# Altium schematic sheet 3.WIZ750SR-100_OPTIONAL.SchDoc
size A4; Team: Wiki
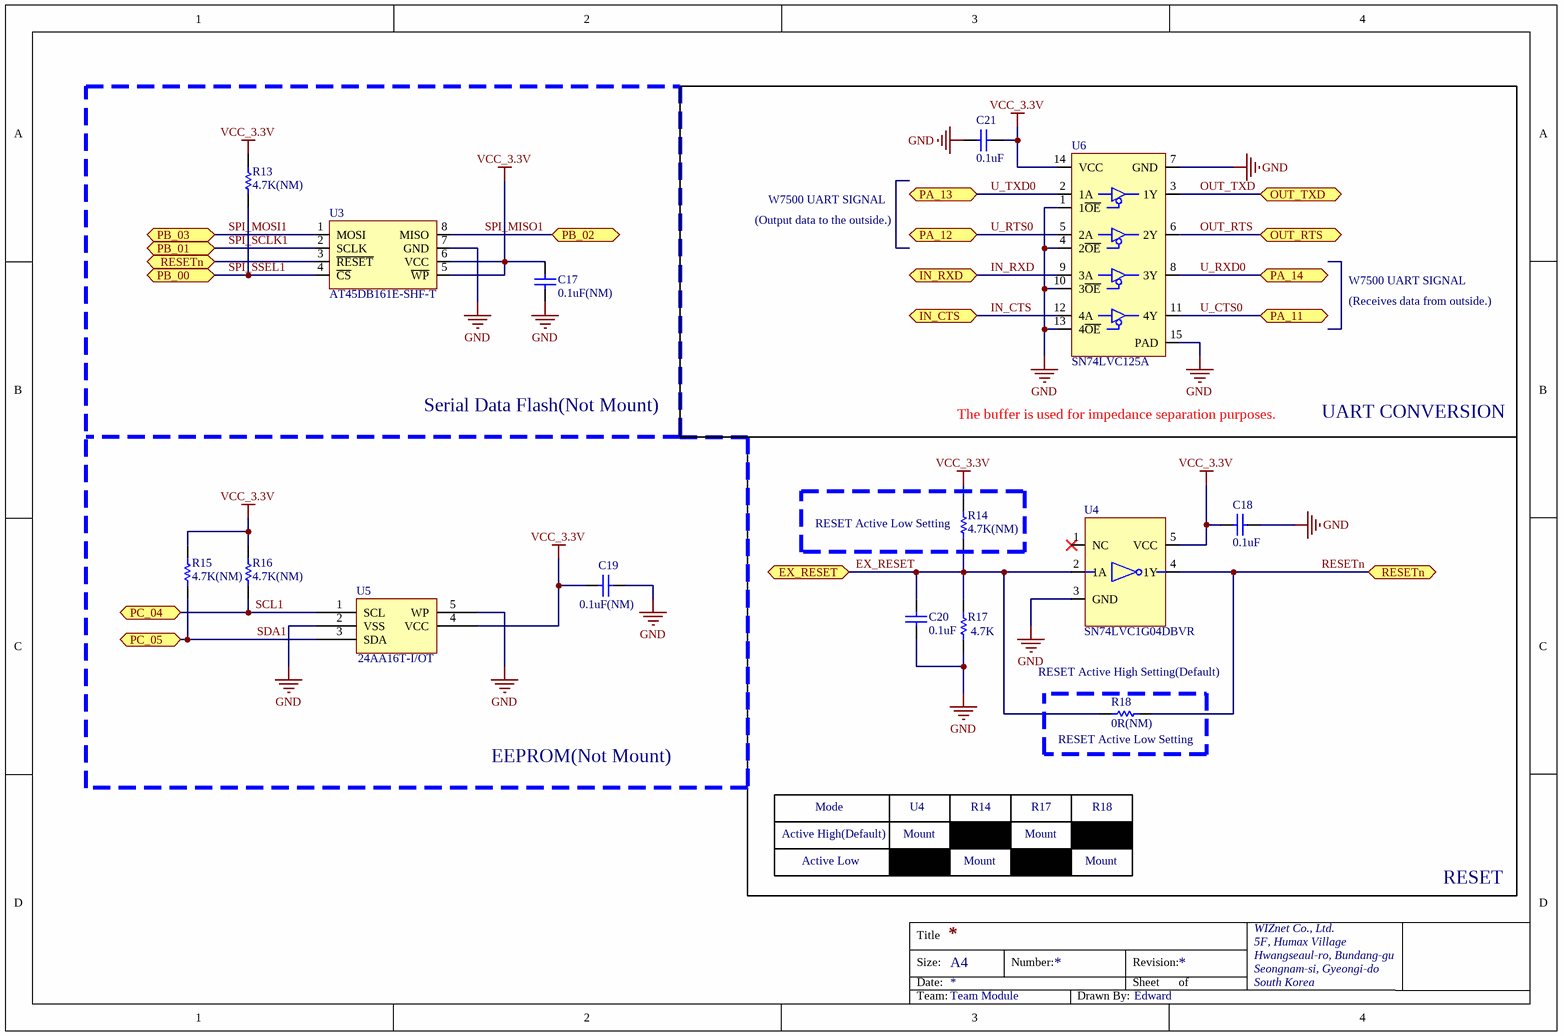
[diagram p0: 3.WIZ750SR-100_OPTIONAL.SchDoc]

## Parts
C17  0.1uF(NM)  [CAP-0402]
C18  0.1uF  [CAP-0402]
C19  0.1uF(NM)  [CAP-0402]
C20  0.1uF  [CAP-0402]
C21  0.1uF  [CAP-0402]
R13  4.7K(NM)  [RES-0402]
R14  4.7K(NM)  [RES-0402]
R15  4.7K(NM)  [RES-0402]
R16  4.7K(NM)  [RES-0402]
R17  4.7K  [RES-0402]
R18  0R(NM)  [RES-0402]
U3  AT45DB161E-SHF-T  [SO-08-EIAJ]
U4  SN74LVC1G04DBVR  [SOT-23-5L]
U5  24AA16T-I/OT  [SOT-23-5L]
U6  SN74LVC125A  [SN74LVC125A]

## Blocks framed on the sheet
UART CONVERSION: C21 U6
RESET: C18 C20 R17 R18 U4
RESET Active Low Setting: R14

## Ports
EX_RESET, IN_CTS, IN_RXD, OUT_RTS, OUT_TXD, PA_11, PA_12, PA_13, PA_14, PB_00, PB_01, PB_02, PB_03, PC_04, PC_05, RESETn

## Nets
GND: C17.2 C18.1 C19.1 C20.1 C21.2 R17.1 U3.7(GND) U4.3(GND) U5.2(VSS) U5.5(WP) U6.1(1~{OE}) U6.4(2~{OE}) U6.7(GND) U6.10(3~{OE}) U6.13(4~{OE}) U6.15(PAD)
VCC_3.3V: C17.1 C18.2 C19.2 C21.1 R13.2 R14.2 R15.2 R16.2 U3.5(~{WP}) U3.6(VCC) U4.5(VCC) U5.4(VCC) U6.14(VCC)
EX_RESET: C20.2 R14.1 R17.2 R18.2 U4.2(1A) ; port EX_RESET
IN_CTS: U6.12(4A) ; port IN_CTS
IN_RXD: U6.9(3A) ; port IN_RXD
OUT_RTS: U6.6(2Y) ; port OUT_RTS
OUT_TXD: U6.3(1Y) ; port OUT_TXD
RESETn: R18.1 U3.3(~{RESET}) U4.4(1Y) ; port RESETn
SCL1: R16.1 U5.1(SCL) ; port PC_04
SDA1: R15.1 U5.3(SDA) ; port PC_05
SPI_MISO1: U3.8(MISO) ; port PB_02
SPI_MOSI1: U3.1(MOSI) ; port PB_03
SPI_SCLK1: U3.2(SCLK) ; port PB_01
SPI_SSEL1: R13.1 U3.4(~{CS}) ; port PB_00
U_CTS0: U6.11(4Y) ; port PA_11
U_RTS0: U6.5(2A) ; port PA_12
U_RXD0: U6.8(3Y) ; port PA_14
U_TXD0: U6.2(1A) ; port PA_13

Not connected (* = marked no-connect by the designer): U4 1(NC)*

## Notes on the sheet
- (Output data to the outside.)
- W7500 UART SIGNAL
- (Receives data from outside.)
- Serial Data Flash(Not Mount)
- The buffer is used for impedance separation purposes.
- (near R18) RESET Active High Setting(Default)
- EEPROM(Not Mount)
- (near R18) RESET Active Low Setting
- Active High(Default)
- Mode
- Mount
- U4
- R14
- R17
- R18
- Active Low

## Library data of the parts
C17-C21 = CAP-0402: Ceramic CAP 0402(1005)
R13-R18 = RES-0402
U3 = AT45DB161E-SHF-T: 16-Mbit DataFlash, 2.3V or 2.5V Minimum SPI Serial Flash Memory
U4 = SN74LVC1G04DBVR: IC, INVERTER, SINGLE, SMD, SOT-23-5
U5 = 24AAxxT-i-OT: SOT-23
U6 = SN74LVC125A: Quadruple Bus Buffer Gate With 3-State Outputs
